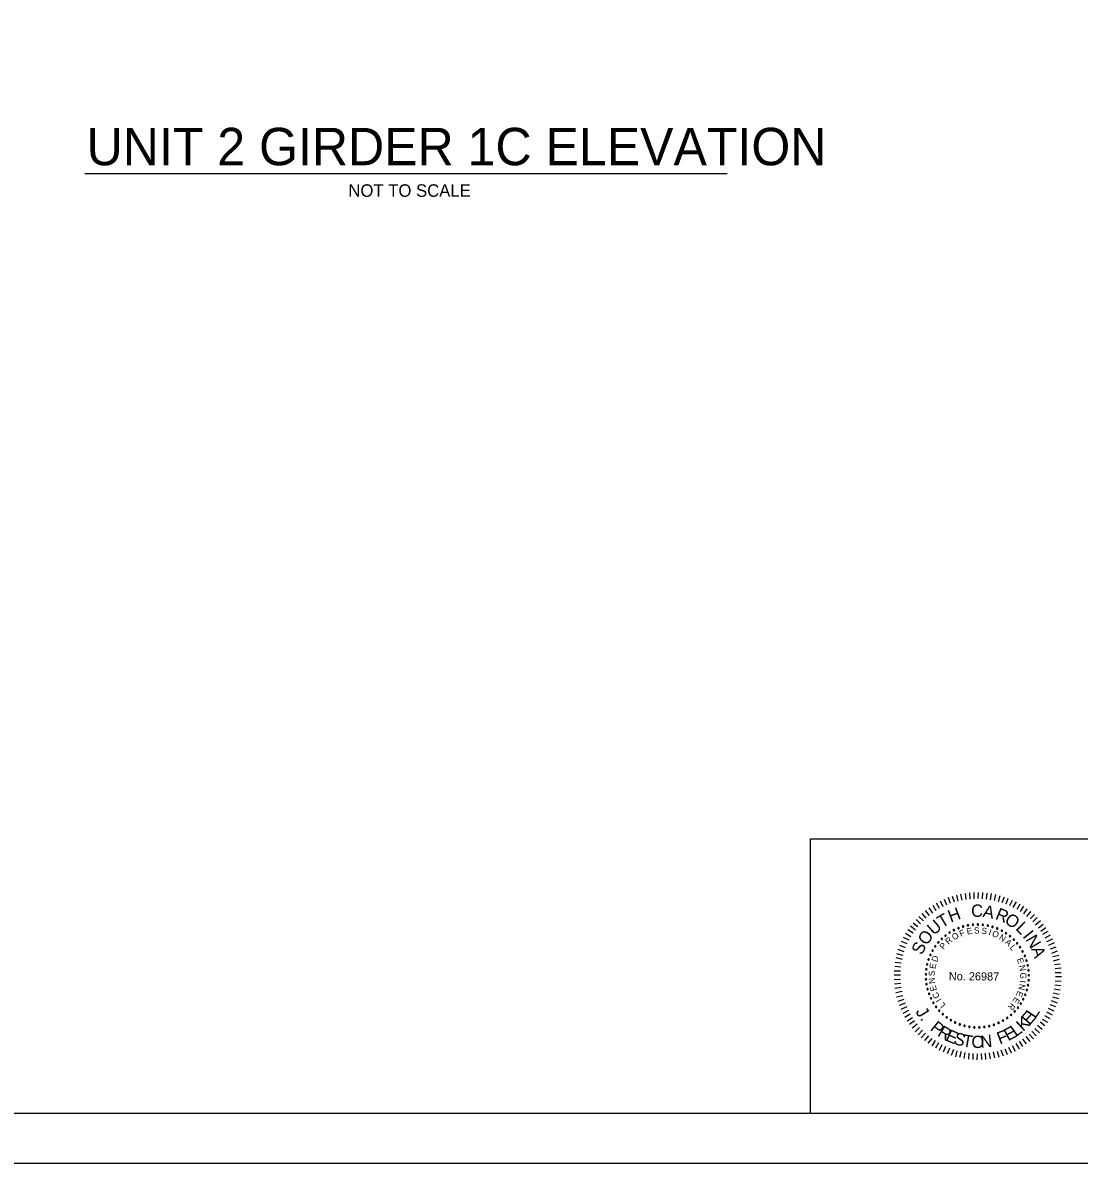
# Model space of a CAD drawing. Extents: x -383 to -161, y -356 to -94.
# Drawn here: x -246.2 to -203.87, y -187.49 to -141.77 of the extents above; entities that cross this region are included whole.
import ezdxf

# ---------------------------------------------------------------- set-up
doc = ezdxf.new("R2010")
doc.units = 0
for name, color, linetype in [('BR_BORDER LINES', 7, 'Continuous'), ('BR_TEXT', 7, 'Continuous'), ('Level 31', 7, 'Continuous')]:
    doc.layers.add(name, color=color, linetype=linetype)

msp = doc.modelspace()

# ---------------------------------------------------------------- linework, layer by layer
at = {"layer": 'BR_BORDER LINES'}
for p, q in [((-214.64, -174.489), (-193.18, -174.489)), ((-214.64, -185.489), (-214.64, -174.489)), ((-297.843, -185.489), (-163.178, -185.489))]:
    msp.add_line(p, q, dxfattribs=at)
at = {"layer": 'BR_TEXT'}
for p, q in [((-243.72, -147.82), (-217.972, -147.82)), ((-209.175, -177.144), (-209.269, -176.92)), ((-209.02, -177.076), (-209.103, -176.842)), ((-208.861, -177.026), (-208.949, -176.795)), ((-208.717, -176.986), (-208.77, -176.742)), ((-208.552, -176.946), (-208.608, -176.709)), ((-208.394, -176.917), (-208.429, -176.673)), ((-208.236, -176.901), (-208.251, -176.657)), ((-208.077, -176.892), (-208.075, -176.634)), ((-207.909, -176.883), (-207.907, -176.636)), ((-207.741, -176.895), (-207.732, -176.637)), ((-207.58, -176.906), (-207.561, -176.663)), ((-207.426, -176.925), (-207.382, -176.681)), ((-207.265, -176.957), (-207.208, -176.721)), ((-207.1, -176.999), (-207.036, -176.756)), ((-206.953, -177.042), (-206.865, -176.813)), ((-206.795, -177.095), (-206.708, -176.862)), ((-209.861, -177.564), (-210.021, -177.363)), ((-209.726, -177.462), (-209.883, -177.258)), ((-209.602, -177.377), (-209.724, -177.16)), ((-209.461, -177.282), (-209.582, -177.065)), ((-209.323, -177.211), (-209.427, -176.987)), ((-206.652, -177.165), (-206.54, -176.942)), ((-206.508, -177.234), (-206.383, -177.012)), ((-206.358, -177.308), (-206.229, -177.093)), ((-206.225, -177.405), (-206.089, -177.19)), ((-206.091, -177.492), (-205.946, -177.291)), ((-210.228, -177.894), (-210.402, -177.724)), ((-210.11, -177.771), (-210.287, -177.594)), ((-209.993, -177.662), (-210.159, -177.482)), ((-205.962, -177.596), (-205.799, -177.398)), ((-205.836, -177.696), (-205.663, -177.519)), ((-205.723, -177.807), (-205.55, -177.634)), ((-205.611, -177.932), (-205.421, -177.765)), ((-210.617, -178.416), (-210.832, -178.287)), ((-210.519, -178.269), (-210.735, -178.137)), ((-210.432, -178.153), (-210.63, -177.993)), ((-210.328, -178.02), (-210.526, -177.864)), ((-205.502, -178.06), (-205.316, -177.907)), ((-205.407, -178.194), (-205.21, -178.038)), ((-205.319, -178.312), (-205.109, -178.183)), ((-210.756, -178.699), (-210.985, -178.598)), ((-210.686, -178.552), (-210.912, -178.441)), ((-205.231, -178.46), (-205.017, -178.335)), ((-205.16, -178.598), (-204.929, -178.49)), ((-205.089, -178.746), (-204.862, -178.648)), ((-210.925, -179.158), (-211.168, -179.098)), ((-210.876, -179.014), (-211.122, -178.923)), ((-210.826, -178.853), (-211.059, -178.766)), ((-205.022, -178.901), (-204.795, -178.817)), ((-204.968, -179.063), (-204.738, -178.976)), ((-204.928, -179.207), (-204.688, -179.151)), ((-211.015, -179.634), (-211.261, -179.605)), ((-210.996, -179.47), (-211.24, -179.437)), ((-210.954, -179.326), (-211.204, -179.262)), ((-204.895, -179.376), (-204.654, -179.316)), ((-204.862, -179.52), (-204.625, -179.491)), ((-204.836, -179.685), (-204.592, -179.66)), ((-211.034, -179.957), (-211.285, -179.955)), ((-211.026, -179.792), (-211.284, -179.79)), ((-204.831, -179.843), (-204.59, -179.845)), ((-204.822, -180.008), (-204.578, -180.01)), ((-211.029, -180.129), (-211.286, -180.133)), ((-211.02, -180.283), (-211.267, -180.312)), ((-211.004, -180.448), (-211.248, -180.484)), ((-204.87, -180.499), (-204.634, -180.538)), ((-204.841, -180.334), (-204.598, -180.367)), ((-204.833, -180.18), (-204.593, -180.189)), ((-210.964, -180.606), (-211.215, -180.659)), ((-210.938, -180.775), (-211.182, -180.831)), ((-210.891, -180.923), (-211.139, -181.006)), ((-204.984, -180.971), (-204.755, -181.059)), ((-204.942, -180.824), (-204.702, -180.885)), ((-204.906, -180.656), (-204.666, -180.713)), ((-210.845, -181.077), (-211.079, -181.161)), ((-210.777, -181.226), (-211.008, -181.334)), ((-210.71, -181.37), (-210.937, -181.489)), ((-205.183, -181.416), (-204.954, -181.538)), ((-205.11, -181.272), (-204.884, -181.384)), ((-205.04, -181.125), (-204.814, -181.213)), ((-210.642, -181.519), (-210.859, -181.644)), ((-210.547, -181.667), (-210.765, -181.792)), ((-210.462, -181.784), (-210.663, -181.93)), ((-210.361, -181.919), (-210.561, -182.075)), ((-205.437, -181.826), (-205.243, -181.975)), ((-205.347, -181.71), (-205.139, -181.839)), ((-205.257, -181.563), (-205.045, -181.692)), ((-210.262, -182.054), (-210.439, -182.217)), ((-210.146, -182.158), (-210.326, -182.338)), ((-210.031, -182.279), (-210.2, -182.463)), ((-209.901, -182.383), (-210.064, -182.57)), ((-205.874, -182.313), (-205.704, -182.5)), ((-205.76, -182.194), (-205.589, -182.377)), ((-205.645, -182.092), (-205.458, -182.258)), ((-205.535, -181.959), (-205.351, -182.118)), ((-209.768, -182.487), (-209.928, -182.678)), ((-209.645, -182.574), (-209.77, -182.782)), ((-209.505, -182.664), (-209.63, -182.879)), ((-209.368, -182.744), (-209.477, -182.967)), ((-209.221, -182.814), (-209.319, -183.037)), ((-206.699, -182.835), (-206.591, -183.059)), ((-206.554, -182.768), (-206.432, -182.992)), ((-206.402, -182.69), (-206.277, -182.907)), ((-206.268, -182.602), (-206.135, -182.812)), ((-206.133, -182.517), (-205.99, -182.71)), ((-206.002, -182.415), (-205.842, -182.605)), ((-209.068, -182.884), (-209.155, -183.11)), ((-208.91, -182.933), (-209.001, -183.166)), ((-208.766, -182.983), (-208.823, -183.219)), ((-208.602, -183.011), (-208.662, -183.258)), ((-208.444, -183.057), (-208.484, -183.29)), ((-208.287, -183.076), (-208.306, -183.323)), ((-208.129, -183.087), (-208.131, -183.335)), ((-207.961, -183.099), (-207.963, -183.343)), ((-207.792, -183.09), (-207.787, -183.338)), ((-207.631, -183.081), (-207.616, -183.329)), ((-207.476, -183.065), (-207.437, -183.299)), ((-207.315, -183.022), (-207.262, -183.27)), ((-207.15, -182.996), (-207.09, -183.233)), ((-207.002, -182.949), (-206.918, -183.183)), ((-206.843, -182.902), (-206.759, -183.13))]:
    msp.add_line(p, q, dxfattribs=at)
for centre, start, end in [((-209.06, -178.248), 32.7576, 212.7576), ((-209.06, -178.248), 212.7576, 32.7576), ((-208.887, -178.149), 27.2191, 207.2191), ((-208.887, -178.149), 207.2191, 27.2191), ((-208.706, -178.067), 21.6807, 201.6807), ((-208.706, -178.067), 201.6807, 21.6807), ((-208.517, -178.003), 16.1422, 196.1422), ((-208.517, -178.003), 196.1422, 16.1422), ((-208.323, -177.957), 10.6038, 190.6038), ((-208.323, -177.957), 190.6038, 10.6038), ((-208.126, -177.93), 5.0653, 185.0653), ((-208.126, -177.93), 185.0653, 5.0653), ((-207.926, -177.923), 359.5268, 179.5268), ((-207.926, -177.923), 179.5268, 359.5268), ((-207.727, -177.934), 173.9884, 353.9884), ((-207.727, -177.934), 353.9884, 173.9884), ((-207.531, -177.965), 168.4499, 348.4499), ((-207.531, -177.965), 348.4499, 168.4499), ((-207.338, -178.015), 162.9114, 342.9114), ((-207.338, -178.015), 342.9114, 162.9114), ((-207.15, -178.083), 157.373, 337.373), ((-207.15, -178.083), 337.373, 157.373), ((-206.97, -178.169), 151.8345, 331.8345), ((-206.97, -178.169), 331.8345, 151.8345), ((-206.8, -178.272), 146.2961, 326.2961), ((-206.8, -178.272), 326.2961, 146.2961), ((-209.511, -178.639), 49.373, 229.373), ((-209.511, -178.639), 229.373, 49.373), ((-209.373, -178.495), 43.8345, 223.8345), ((-209.373, -178.495), 223.8345, 43.8345), ((-209.223, -178.364), 38.2961, 218.2961), ((-209.223, -178.364), 218.2961, 38.2961), ((-206.639, -178.39), 140.7576, 320.7576), ((-206.639, -178.39), 320.7576, 140.7576), ((-206.492, -178.524), 135.2191, 315.2191), ((-206.492, -178.524), 315.2191, 135.2191), ((-206.357, -178.671), 129.6807, 309.6807), ((-206.357, -178.671), 309.6807, 129.6807), ((-209.83, -179.142), 65.9884, 245.9884), ((-209.83, -179.142), 245.9884, 65.9884), ((-209.74, -178.964), 60.4499, 240.4499), ((-209.74, -178.964), 240.4499, 60.4499), ((-209.633, -178.796), 54.9114, 234.9114), ((-209.633, -178.796), 234.9114, 54.9114), ((-206.238, -178.831), 124.1422, 304.1422), ((-206.238, -178.831), 304.1422, 124.1422), ((-206.135, -179.001), 118.6038, 298.6038), ((-206.135, -179.001), 298.6038, 118.6038), ((-206.048, -179.181), 113.0653, 293.0653), ((-206.048, -179.181), 293.0653, 113.0653), ((-209.957, -179.52), 77.0653, 257.0653), ((-209.957, -179.52), 257.0653, 77.0653), ((-209.903, -179.328), 71.5268, 251.5268), ((-209.903, -179.328), 251.5268, 71.5268), ((-205.979, -179.368), 107.5268, 287.5268), ((-205.979, -179.368), 287.5268, 107.5268), ((-205.929, -179.561), 101.9884, 281.9884), ((-205.929, -179.561), 281.9884, 101.9884), ((-210.009, -179.914), 88.1422, 268.1422), ((-210.006, -180.114), 93.6807, 273.6807), ((-209.993, -179.716), 82.6038, 262.6038), ((-210.009, -179.914), 268.1422, 88.1422), ((-210.006, -180.114), 273.6807, 93.6807), ((-209.993, -179.716), 262.6038, 82.6038), ((-205.897, -179.758), 96.4499, 276.4499), ((-205.885, -179.957), 90.9114, 270.9114), ((-205.897, -179.758), 276.4499, 96.4499), ((-205.885, -179.957), 270.9114, 90.9114), ((-209.984, -180.312), 99.2191, 279.2191), ((-209.984, -180.312), 279.2191, 99.2191), ((-209.943, -180.507), 104.7576, 284.7576), ((-209.943, -180.507), 284.7576, 104.7576), ((-205.963, -180.548), 74.2961, 254.2961), ((-205.963, -180.548), 254.2961, 74.2961), ((-205.918, -180.353), 79.8345, 259.8345), ((-205.918, -180.353), 259.8345, 79.8345), ((-205.892, -180.156), 85.373, 265.373), ((-205.892, -180.156), 265.373, 85.373), ((-209.884, -180.697), 110.2961, 290.2961), ((-209.884, -180.697), 290.2961, 110.2961), ((-209.806, -180.881), 115.8345, 295.8345), ((-209.806, -180.881), 295.8345, 115.8345), ((-209.711, -181.056), 121.373, 301.373), ((-209.711, -181.056), 301.373, 121.373), ((-206.108, -180.918), 63.2191, 243.2191), ((-206.108, -180.918), 243.2191, 63.2191), ((-206.026, -180.737), 68.7576, 248.7576), ((-206.026, -180.737), 248.7576, 68.7576), ((-209.599, -181.221), 126.9114, 306.9114), ((-209.599, -181.221), 306.9114, 126.9114), ((-209.472, -181.375), 132.4499, 312.4499), ((-209.472, -181.375), 312.4499, 132.4499), ((-209.331, -181.515), 317.9884, 137.9884), ((-206.452, -181.406), 46.6038, 226.6038), ((-206.452, -181.406), 226.6038, 46.6038), ((-206.321, -181.255), 52.1422, 232.1422), ((-206.321, -181.255), 232.1422, 52.1422), ((-206.207, -181.092), 57.6807, 237.6807), ((-206.207, -181.092), 237.6807, 57.6807), ((-209.331, -181.515), 137.9884, 317.9884), ((-209.177, -181.642), 143.5268, 323.5268), ((-209.177, -181.642), 323.5268, 143.5268), ((-209.011, -181.753), 149.0653, 329.0653), ((-209.011, -181.753), 329.0653, 149.0653), ((-208.836, -181.847), 154.6038, 334.6038), ((-208.836, -181.847), 334.6038, 154.6038), ((-208.652, -181.924), 160.1422, 340.1422), ((-208.652, -181.924), 340.1422, 160.1422), ((-207.283, -181.938), 18.9114, 198.9114), ((-207.283, -181.938), 198.9114, 18.9114), ((-207.098, -181.865), 24.4499, 204.4499), ((-207.098, -181.865), 204.4499, 24.4499), ((-206.92, -181.774), 29.9884, 209.9884), ((-206.92, -181.774), 209.9884, 29.9884), ((-206.752, -181.667), 35.5268, 215.5268), ((-206.752, -181.667), 215.5268, 35.5268), ((-206.596, -181.543), 41.0653, 221.0653), ((-206.596, -181.543), 221.0653, 41.0653), ((-208.462, -181.983), 165.6807, 345.6807), ((-208.462, -181.983), 345.6807, 165.6807), ((-208.267, -182.023), 171.2191, 351.2191), ((-208.267, -182.023), 351.2191, 171.2191), ((-208.068, -182.045), 356.7576, 176.7576), ((-208.068, -182.045), 176.7576, 356.7576), ((-207.869, -182.047), 2.2961, 182.2961), ((-207.869, -182.047), 182.2961, 2.2961), ((-207.67, -182.029), 7.8345, 187.8345), ((-207.67, -182.029), 187.8345, 7.8345), ((-207.474, -181.993), 13.373, 193.373), ((-207.474, -181.993), 193.373, 13.373)]:
    msp.add_arc(centre, 0.028, start, end, dxfattribs=at)
at = {"layer": 'Level 31'}
msp.add_lwpolyline([(-305.176, -187.489), (-161.176, -187.489), (-161.176, -99.489), (-305.176, -99.489)], close=True, dxfattribs=at)

# ---------------------------------------------------------------- texts
at = {"layer": 'BR_TEXT'}
for s, height, p in [('UNIT 2 GIRDER 1C ELEVATION', 1.5, (-243.643, -147.483)), ('NOT TO SCALE', 0.5, (-233.153, -148.747))]:
    msp.add_text(s, height=height, dxfattribs=at).set_placement(p)
for s, height, rotation, p in [('H', 0.496, 20.3637, (-209.018, -177.846)), ('C', 0.496, 359.5482, (-208.2, -177.612)), ('A', 0.496, 348.1981, (-207.755, -177.609)), ('R', 0.496, 337.4344, (-207.262, -177.689)), ('U', 0.496, 40.8022, (-209.694, -178.375)), ('T', 0.496, 30.4992, (-209.37, -178.076)), ('O', 0.496, 326.5869, (-206.893, -177.836)), ('L', 0.496, 315.9488, (-206.442, -178.107)), ('O', 0.496, 52.0267, (-209.993, -178.79)), ('O', 0.249, 30.8477, (-208.882, -178.561)), ('F', 0.249, 20.6127, (-208.613, -178.417)), ('E', 0.249, 11.4103, (-208.352, -178.33)), ('S', 0.249, 2.208, (-208.081, -178.286)), ('S', 0.249, 352.6608, (-207.796, -178.287)), ('I', 0.249, 343.1136, (-207.515, -178.335)), ('O', 0.249, 338.4392, (-207.381, -178.376)), ('I', 0.496, 308.6613, (-206.157, -178.404)), ('S', 0.496, 63.2511, (-210.174, -179.173)), ('P', 0.249, 49.9421, (-209.299, -178.947)), ('R', 0.249, 40.3949, (-209.107, -178.737)), ('N', 0.249, 328.2042, (-207.103, -178.501)), ('A', 0.249, 318.657, (-206.867, -178.662)), ('L', 0.249, 309.4546, (-206.668, -178.851)), ('N', 0.496, 300.7037, (-206.035, -178.521)), ('D', 0.249, 69.0364, (-209.567, -179.448)), ('A', 0.496, 289.4792, (-205.798, -178.894)), ('E', 0.249, 78.2388, (-209.633, -179.715)), ('E', 0.249, 291.049, (-206.372, -179.312)), ('N', 0.249, 281.8466, (-206.283, -179.572)), ('S', 0.249, 87.786, (-209.656, -179.999)), ('N', 0.249, 97.3332, (-209.632, -180.283)), ('No. 26987', 0.327, 359.5268, (-209.092, -180.153)), ('G', 0.249, 272.2995, (-206.237, -179.853)), ('E', 0.249, 106.5355, (-209.564, -180.549)), ('N', 0.249, 257.7339, (-206.256, -180.287)), ('I', 0.249, 262.4084, (-206.238, -180.149)), ('C', 0.249, 116.4266, (-209.444, -180.819)), ('I', 0.249, 121.1011, (-209.372, -180.939)), ('L', 0.249, 129.9595, (-209.209, -181.147)), ('E', 0.249, 238.9844, (-206.44, -180.814)), ('E', 0.249, 248.1867, (-206.328, -180.563)), ('J', 0.494, 302.9559, (-210.441, -181.421)), ('R', 0.249, 229.782, (-206.591, -181.044)), ('E', 0.494, 49.3639, (-205.857, -181.989)), ('L', 0.494, 56.4247, (-205.627, -181.718)), ('.', 0.494, 309.3974, (-210.264, -181.693)), ('P', 0.494, 321.1035, (-209.871, -182.13)), ('K', 0.494, 42.3031, (-206.118, -182.229)), ('R', 0.494, 328.5359, (-209.578, -182.362)), ('E', 0.494, 335.9684, (-209.257, -182.555)), ('S', 0.494, 343.0292, (-208.932, -182.698)), ('T', 0.494, 350.4617, (-208.573, -182.804)), ('O', 0.494, 358.1419, (-208.192, -182.863)), ('N', 0.494, 5.8221, (-207.805, -182.872)), ('F', 0.494, 21.1206, (-207.05, -182.735)), ('E', 0.494, 28.1814, (-206.719, -182.605)), ('L', 0.494, 35.2422, (-206.407, -182.436))]:
    msp.add_text(s, height=height, rotation=rotation, dxfattribs=at).set_placement(p)

doc.saveas('drawing.dxf')
